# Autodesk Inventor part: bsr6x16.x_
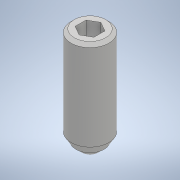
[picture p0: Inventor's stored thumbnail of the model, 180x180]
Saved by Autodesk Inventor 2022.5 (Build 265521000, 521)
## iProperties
Created: 2020-01
Part Number: bsr6x16.x_
Material: 一般
Document SubType Name: Modeling
Designer: ImaoCorp
Density: 1 g/cm^3
Appearance: 既定
Sending System: SOLIDWORKS 2018-2018316
MC: AMD64
MC_MODEL: Intel64 Family 6 Model 60 Stepping 3, GenuineIntel
OS: Windows_NT
FRU: Parasolid Version 30.0, build 310,  6- 8-2018
FORMAT: text
GUISE: transmit
KEY: bsr6x16
FILE: bsr6x16.x_t
DATE: Thu Jan 23 16:47:08 2020
Author: ImaoCorp
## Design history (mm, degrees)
feature "Base1"
node "ソリッド1"
